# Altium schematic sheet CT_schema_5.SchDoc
size 260 x 245 mm
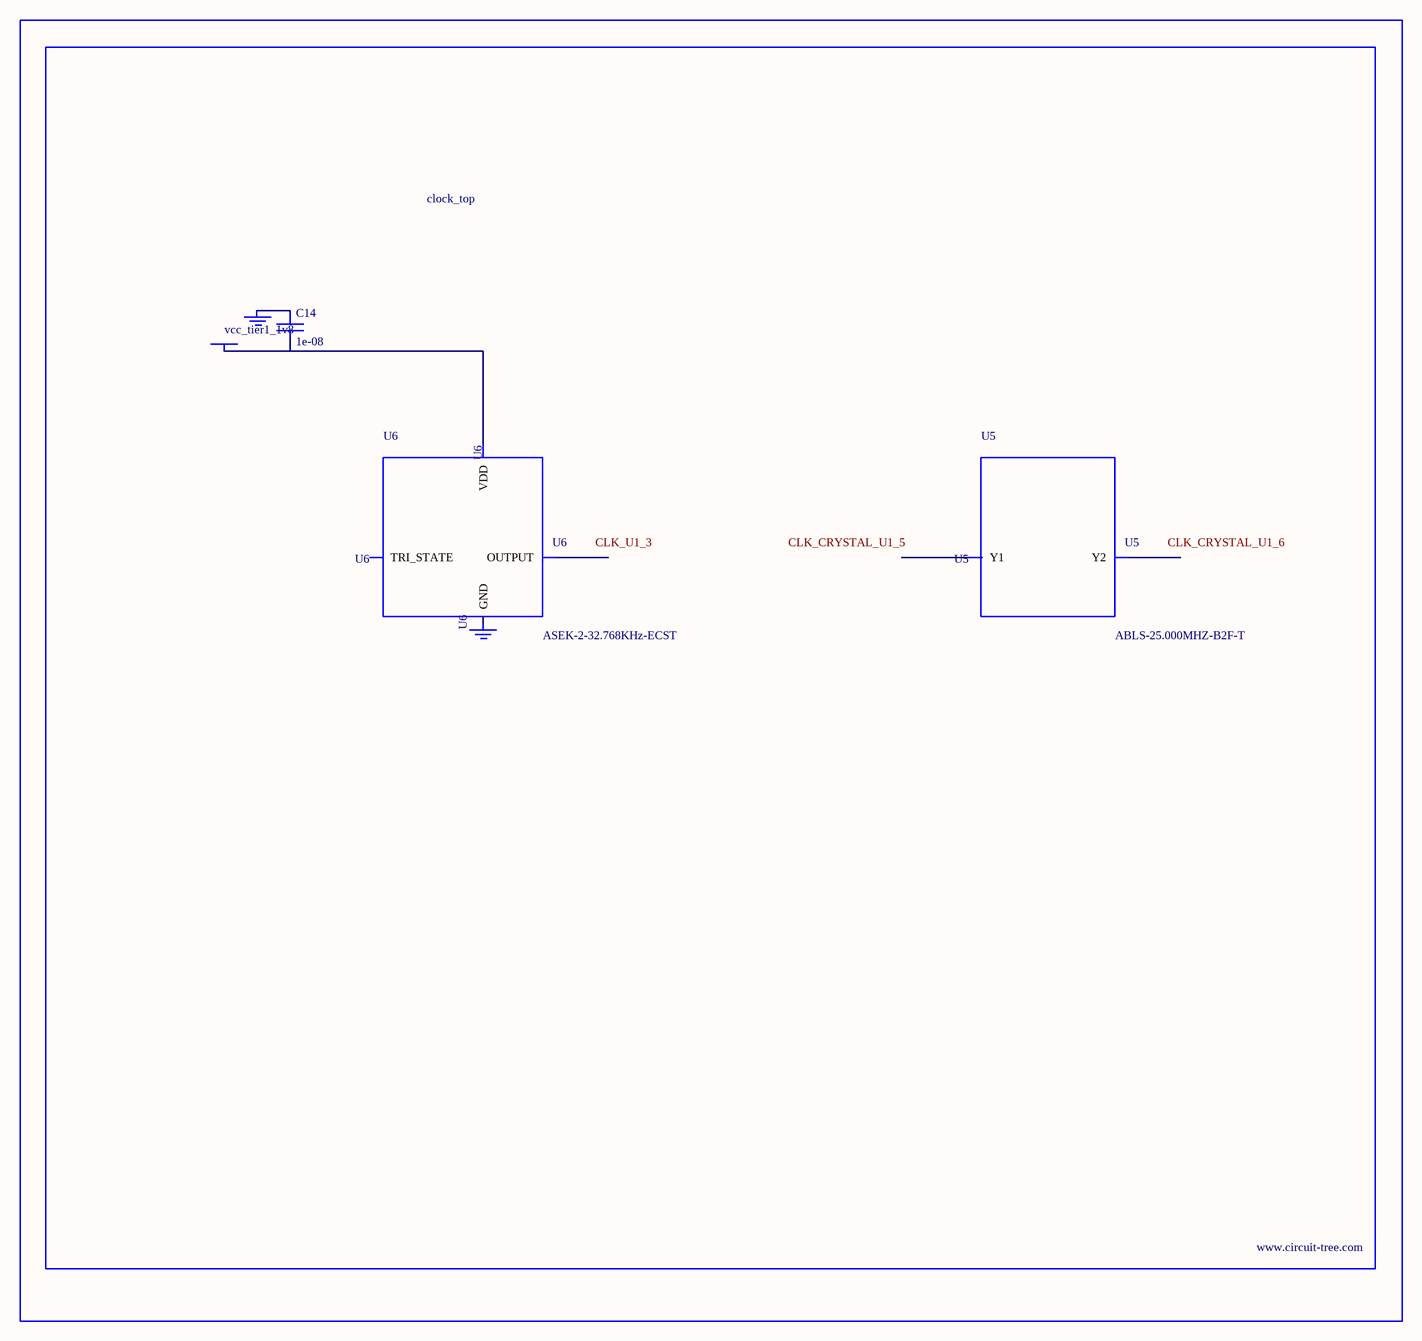
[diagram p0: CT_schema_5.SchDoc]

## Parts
BORDER4  (no value)
C14  1e-08  [C0402]
GND_INSTANCE_4_0  (no value)
GND_INSTANCE_4_1  (no value)
POWER_INSTANCE_4_0  vcc_tier1_1v8
U5  ABLS-25.000MHZ-B2F-T  [ABLS-25.000MHZ-B2F-T]
U6  ASEK-2-32.768KHz-ECST  [ASEK]

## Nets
NetC14_1: C14.1 GND_INSTANCE_4_0.0(GND)
NetC14_2: C14.2 POWER_INSTANCE_4_0.0(PWR) U6.4(VDD)

Not connected (* = marked no-connect by the designer): GND_INSTANCE_4_1 0(GND); U5 1(Y1) 2(Y2); U6 1(TRI_STATE) 2(GND) 3(OUTPUT)

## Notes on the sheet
- Labels drawn without touching a wire or pin: CLK_CRYSTAL_U1_5, CLK_CRYSTAL_U1_6, CLK_U1_3

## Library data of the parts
BORDER4 = BORDER_PAGE4
C14 = C0402C103K3RAC
GND_INSTANCE_4_0 GND_INSTANCE_4_1 = GND
POWER_INSTANCE_4_0 = PWR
